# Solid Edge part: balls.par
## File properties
Title: Bearing
Author: Abhinav Rai
Template: Normal.par
Last saved by: Cadcim
Revision: 9
Application: Solid Edge
Material: aluminum
Accuracy: 0.99
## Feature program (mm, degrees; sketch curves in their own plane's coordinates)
sketch for "unnamed RevolvedProtrusion 1" plane through (0, 0, 0) normal (0, -1, 0) x-axis (1, 0, 0)
  arc centre (0, 0) radius 6.604 from (0, 6.604) to (0, -6.604) cw
  line (0, 6.604) -> (0, -6.604)
revolve "unnamed RevolvedProtrusion 1" add full turn 360 deg
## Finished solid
Body 1: solid body, 1 face, 0 edges, 0 vertices.
  Faces by surface: sphere 1
Spherical faces by radius (mm): R6.604 x1
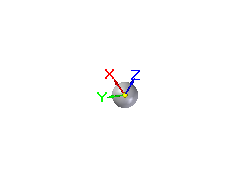
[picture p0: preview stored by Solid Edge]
